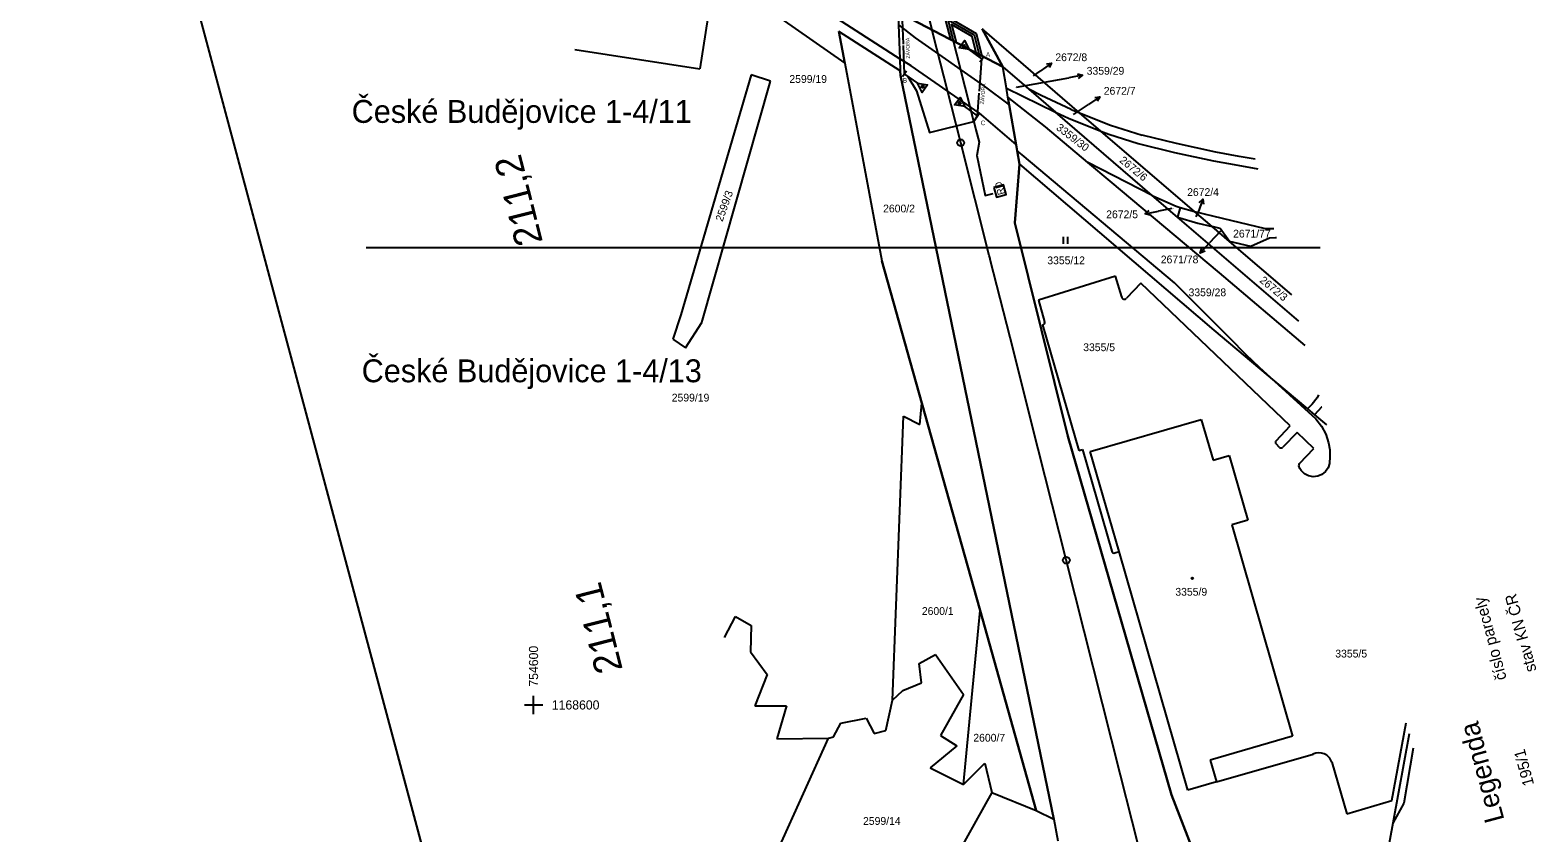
# Model space of a CAD drawing. Extents: x -754710 to -754206, y -1169123 to -1168234.
# Drawn here: x -754710 to -754380.5, y -1168628 to -1168452.5 of the extents above; entities that cross this region are included whole.
import ezdxf

# ---------------------------------------------------------------- set-up
doc = ezdxf.new("R2010")
doc.units = 0
for name, color, linetype in [('Implicitní', 7, 'Continuous'), ('Vrstva 1', 7, 'Continuous'), ('Vrstva 10', 7, 'Continuous'), ('Vrstva 16', 7, 'Continuous'), ('Vrstva 18', 7, 'Continuous'), ('Vrstva 19', 7, 'Continuous'), ('Vrstva 23', 7, 'Continuous'), ('Vrstva 25', 7, 'Continuous'), ('Vrstva 3', 7, 'Continuous'), ('Vrstva 4', 7, 'Continuous'), ('Vrstva 45', 7, 'Continuous'), ('Vrstva 6', 7, 'Continuous'), ('Vrstva 61', 7, 'Continuous'), ('Vrstva 7', 7, 'Continuous')]:
    doc.layers.add(name, color=color, linetype=linetype)

msp = doc.modelspace()

# ---------------------------------------------------------------- linework, layer by layer
at = {"layer": 'Implicitní'}
for points in [[(-754600, -1168602), (-754600, -1168600), (-754600, -1168598)], [(-754602, -1168600), (-754600, -1168600), (-754598, -1168600)]]:
    msp.add_lwpolyline(points, dxfattribs=at)
at = {"layer": 'Vrstva 1'}
for p, q in [((-754560.36, -1168439.85), (-754563.64, -1168460.96)), ((-754543.86, -1168443.35), (-754519.95, -1168458.75)), ((-754517.36, -1168450.11), (-754497.45, -1168460.53)), ((-754517.36, -1168450.11), (-754497.45, -1168460.53)), ((-754531.99, -1168459.75), (-754533.3, -1168452.78)), ((-754519.84, -1168461.42), (-754533.3, -1168452.78)), ((-754533.3, -1168452.78), (-754531.99, -1168459.75)), ((-754519.84, -1168461.42), (-754533.3, -1168452.78)), ((-754520.25, -1168451.35), (-754519.95, -1168458.75)), ((-754497.45, -1168460.53), (-754501.97, -1168452.25)), ((-754501.97, -1168452.25), (-754497.45, -1168460.53)), ((-754480.66, -1168470.56), (-754501.97, -1168452.25)), ((-754590.98, -1168456.71), (-754563.64, -1168460.96)), ((-754531.99, -1168459.75), (-754523.85, -1168502.96)), ((-754531.99, -1168459.75), (-754523.85, -1168502.96)), ((-754519.95, -1168458.75), (-754519.84, -1168461.42)), ((-754552.4, -1168462.3), (-754567.78, -1168514.73)), ((-754548.2, -1168463.7), (-754552.4, -1168462.3)), ((-754519.8, -1168462.41), (-754519.84, -1168461.42)), ((-754519.84, -1168461.42), (-754519.8, -1168462.41)), ((-754486.32, -1168624.94), (-754519.8, -1168462.41)), ((-754519.8, -1168462.41), (-754486.32, -1168624.94)), ((-754496.66, -1168465.16), (-754497.45, -1168460.53)), ((-754497.45, -1168460.53), (-754491.78, -1168465.4)), ((-754563.21, -1168516.41), (-754548.2, -1168463.7)), ((-754496.32, -1168467.13), (-754496.66, -1168465.16)), ((-754496.66, -1168465.16), (-754485.92, -1168470.44)), ((-754489.05, -1168466.81), (-754491.78, -1168465.4)), ((-754491.78, -1168465.4), (-754485.92, -1168470.44)), ((-754496.32, -1168467.13), (-754496.03, -1168468.86)), ((-754488.07, -1168473.66), (-754496.32, -1168467.13)), ((-754496.03, -1168468.86), (-754494.55, -1168477.55)), ((-754482.46, -1168469.84), (-754489.05, -1168466.81)), ((-754482.46, -1168469.84), (-754480.66, -1168470.56)), ((-754485.92, -1168470.44), (-754483.05, -1168471.75)), ((-754464.78, -1168488.62), (-754485.92, -1168470.44)), ((-754483.05, -1168471.75), (-754475.99, -1168474.58)), ((-754475.99, -1168474.58), (-754480.66, -1168470.56)), ((-754480.66, -1168470.56), (-754473.87, -1168473.28)), ((-754473.87, -1168473.28), (-754467, -1168475.47)), ((-754478.83, -1168481.43), (-754488.07, -1168473.66)), ((-754475.99, -1168474.58), (-754474.28, -1168475.26)), ((-754455.54, -1168492.15), (-754475.99, -1168474.58)), ((-754474.28, -1168475.26), (-754467.84, -1168477.28)), ((-754459.45, -1168477.29), (-754467, -1168475.47)), ((-754494.55, -1168477.55), (-754494.32, -1168478.89)), ((-754494.32, -1168478.89), (-754493.82, -1168481.8)), ((-754467.84, -1168477.28), (-754459.92, -1168479.25)), ((-754459.92, -1168479.25), (-754451.42, -1168481.08)), ((-754450.91, -1168479.15), (-754459.45, -1168477.29)), ((-754445.75, -1168480.12), (-754450.91, -1168479.15)), ((-754493.82, -1168481.8), (-754494.84, -1168494.63)), ((-754493.82, -1168481.8), (-754451.31, -1168518.1)), ((-754464.78, -1168488.62), (-754478.83, -1168481.43)), ((-754474, -1168485.49), (-754478.83, -1168481.43)), ((-754451.42, -1168481.08), (-754446.07, -1168482.05)), ((-754446.07, -1168482.05), (-754441.7, -1168482.79)), ((-754442.25, -1168480.73), (-754445.75, -1168480.12)), ((-754450.1, -1168505.56), (-754474, -1168485.49)), ((-754459.22, -1168493.4), (-754464.78, -1168488.62)), ((-754464.78, -1168488.62), (-754464, -1168489.01)), ((-754464, -1168489.01), (-754459.55, -1168491)), ((-754459.55, -1168491), (-754458.66, -1168491.26)), ((-754458.66, -1168491.26), (-754459.22, -1168493.4)), ((-754458.66, -1168491.26), (-754455.54, -1168492.15)), ((-754451.69, -1168495.45), (-754455.54, -1168492.15)), ((-754455.54, -1168492.15), (-754449.48, -1168493.64)), ((-754494.84, -1168494.63), (-754483.21, -1168541.23)), ((-754459.22, -1168493.4), (-754454.78, -1168494.69)), ((-754432.76, -1168516.15), (-754459.22, -1168493.4)), ((-754454.78, -1168494.69), (-754451.69, -1168495.45)), ((-754449.92, -1168495.89), (-754451.69, -1168495.45)), ((-754447.92, -1168498.69), (-754451.69, -1168495.45)), ((-754447.92, -1168498.69), (-754449.92, -1168495.89)), ((-754449.48, -1168493.64), (-754440.12, -1168495.87)), ((-754440.12, -1168495.87), (-754438.19, -1168495.88)), ((-754443.24, -1168499.78), (-754447.92, -1168498.69)), ((-754434.3, -1168510.39), (-754447.92, -1168498.69)), ((-754439.15, -1168497.98), (-754443.24, -1168499.78)), ((-754437.86, -1168497.94), (-754439.15, -1168497.98)), ((-754437.64, -1168497.93), (-754437.86, -1168497.94)), ((-754523.85, -1168502.96), (-754515.13, -1168534.05)), ((-754515.13, -1168534.05), (-754523.85, -1168502.96)), ((-754472.79, -1168506.27), (-754489.67, -1168511.5)), ((-754471.44, -1168510.82), (-754472.79, -1168506.27)), ((-754431.34, -1168521.47), (-754450.1, -1168505.56)), ((-754467.28, -1168507.81), (-754470.39, -1168511.07)), ((-754434.63, -1168539.02), (-754467.28, -1168507.81)), ((-754489.67, -1168511.5), (-754488.29, -1168516.29)), ((-754567.78, -1168514.73), (-754569.52, -1168520.08)), ((-754566.76, -1168521.95), (-754563.21, -1168516.41)), ((-754488.79, -1168516.94), (-754480.84, -1168544.38)), ((-754451.31, -1168518.1), (-754438.06, -1168529.24)), ((-754569.52, -1168520.08), (-754566.76, -1168521.95)), ((-754438.06, -1168529.24), (-754429.01, -1168537.46)), ((-754438.06, -1168529.24), (-754430.86, -1168535.3)), ((-754428.46, -1168532.2), (-754428.74, -1168532.86)), ((-754515.13, -1168534.05), (-754502.42, -1168579.34)), ((-754502.42, -1168579.34), (-754515.13, -1168534.05)), ((-754429.84, -1168534.28), (-754430.86, -1168535.3)), ((-754430.86, -1168535.3), (-754429.3, -1168536.61)), ((-754428.74, -1168532.86), (-754429.84, -1168534.28)), ((-754427.75, -1168534.95), (-754429.3, -1168536.61)), ((-754427.73, -1168534.92), (-754427.75, -1168534.95)), ((-754478.33, -1168544.59), (-754454.05, -1168537.59)), ((-754454.05, -1168537.59), (-754451.48, -1168546.52)), ((-754437.72, -1168542.25), (-754434.63, -1168539.02)), ((-754429.3, -1168536.61), (-754426.69, -1168538.8)), ((-754429.01, -1168537.46), (-754427.79, -1168539.04)), ((-754427.79, -1168539.04), (-754426.86, -1168540.83)), ((-754483.21, -1168541.23), (-754460.6, -1168619.67)), ((-754433.1, -1168540.48), (-754436.22, -1168543.69)), ((-754429.48, -1168543.95), (-754433.1, -1168540.48)), ((-754426.86, -1168540.83), (-754426.25, -1168542.73)), ((-754480.84, -1168544.38), (-754480.05, -1168544.18)), ((-754480.05, -1168544.18), (-754473.59, -1168566.41)), ((-754472.02, -1168566.47), (-754478.33, -1168544.59)), ((-754451.48, -1168546.52), (-754447.94, -1168545.46)), ((-754447.94, -1168545.46), (-754443.9, -1168559.58)), ((-754436.93, -1168543.71), (-754437.7, -1168542.95)), ((-754432.61, -1168547.25), (-754429.48, -1168543.95)), ((-754426.25, -1168542.73), (-754425.99, -1168544.22)), ((-754425.93, -1168545.71), (-754426.04, -1168547.24)), ((-754425.99, -1168544.22), (-754425.93, -1168545.71)), ((-754432.73, -1168547.73), (-754432.61, -1168547.25)), ((-754432.51, -1168548.29), (-754432.73, -1168547.73)), ((-754432.22, -1168548.77), (-754432.51, -1168548.29)), ((-754431.49, -1168549.46), (-754432.22, -1168548.77)), ((-754426.9, -1168548.99), (-754427.68, -1168549.62)), ((-754426.32, -1168548.19), (-754426.9, -1168548.99)), ((-754426.04, -1168547.24), (-754426.32, -1168548.19)), ((-754430.61, -1168549.91), (-754431.49, -1168549.46)), ((-754429.64, -1168550.11), (-754430.61, -1168549.91)), ((-754428.62, -1168549.99), (-754429.64, -1168550.11)), ((-754427.68, -1168549.62), (-754428.62, -1168549.99)), ((-754443.9, -1168559.58), (-754447.41, -1168560.64)), ((-754447.41, -1168560.64), (-754434.1, -1168606.84)), ((-754471.68, -1168615.35), (-754483.58, -1168568.3)), ((-754472.98, -1168566.77), (-754472.02, -1168566.47)), ((-754456.98, -1168618.63), (-754472.02, -1168566.47)), ((-754502.42, -1168579.34), (-754490.14, -1168623.07)), ((-754490.14, -1168623.07), (-754502.42, -1168579.34)), ((-754412.42, -1168620.92), (-754409.25, -1168603.88)), ((-754434.1, -1168606.84), (-754452.14, -1168612.04)), ((-754408.6, -1168606.31), (-754412.19, -1168625.83)), ((-754450.76, -1168616.84), (-754429.64, -1168610.75)), ((-754407.76, -1168609.45), (-754409.8, -1168621.48)), ((-754452.14, -1168612.04), (-754450.76, -1168616.84)), ((-754425.55, -1168612.51), (-754422.27, -1168623.78)), ((-754463.59, -1168647.3), (-754471.68, -1168615.35)), ((-754450.76, -1168616.84), (-754456.98, -1168618.63)), ((-754460.6, -1168619.67), (-754452.67, -1168639.96)), ((-754422.27, -1168623.78), (-754412.42, -1168620.92)), ((-754409.8, -1168621.48), (-754412.19, -1168625.83)), ((-754490.14, -1168623.07), (-754486.32, -1168624.94)), ((-754490.14, -1168623.07), (-754486.32, -1168624.94)), ((-754486.32, -1168624.94), (-754485.38, -1168629.68)), ((-754412.19, -1168625.83), (-754413.36, -1168632.2))]:
    msp.add_line(p, q, dxfattribs=at)
for points in [[(-754483.58, -1168568.3), (-754489.69, -1168544.13), (-754495.86, -1168519.7), (-754500.17, -1168502.64), (-754500.22, -1168502.46), (-754500.39, -1168501.79), (-754506.63, -1168477.15), (-754508.73, -1168468.84), (-754512.62, -1168453.46), (-754513.24, -1168451.02), (-754516.47, -1168438.36), (-754517.79, -1168433.24), (-754523.55, -1168411.48), (-754527.19, -1168398.27), (-754531.51, -1168382.98), (-754533.99, -1168374.26), (-754535.88, -1168367.71), (-754539.68, -1168354.44)], [(-754519.17, -1168455.59), (-754519.47, -1168446.86)], [(-754452.67, -1168639.96), (-754460.6, -1168619.67), (-754483.21, -1168541.23), (-754494.84, -1168494.63), (-754493.82, -1168481.8), (-754494.32, -1168478.89), (-754494.55, -1168477.55), (-754496.03, -1168468.86), (-754496.32, -1168467.13), (-754496.66, -1168465.16), (-754497.45, -1168460.53), (-754517.36, -1168450.11), (-754520.37, -1168448.54), (-754520.33, -1168449.52), (-754520.25, -1168451.35), (-754519.95, -1168458.75), (-754519.84, -1168461.42), (-754519.8, -1168462.41), (-754486.32, -1168624.94), (-754485.38, -1168629.68)], [(-754518.94, -1168462.12), (-754519.16, -1168455.85)], [(-754502.54, -1168465.84), (-754501.99, -1168458.81)], [(-754502.96, -1168471.26), (-754502.57, -1168466.27)]]:
    msp.add_lwpolyline(points, dxfattribs=at)
for centre in [(-754506.63, -1168477.14), (-754483.56, -1168568.36), (-754483.56, -1168568.36)]:
    msp.add_circle(centre, 0.75, dxfattribs=at)
for centre, radius, start, end in [((-754470.87, -1168510.77), 0.567, 184.6224, 328.5926), ((-754488.79, -1168516.42), 0.517, 269.9303, 14.9325), ((-754437.38, -1168542.59), 0.482, 135.0258, 228.2473), ((-754436.59, -1168543.32), 0.518, 228.3065, 314.9206), ((-754473.14, -1168566.34), 0.458, 188.7847, 290.1201), ((-754428.36, -1168613.4), 2.94, 17.5572, 115.8766)]:
    msp.add_arc(centre, radius, start, end, dxfattribs=at)
at = {"layer": 'Vrstva 10'}
msp.add_lwpolyline([(-754509.03, -1168449.86), (-754503.24, -1168453.23), (-754502.05, -1168458.12), (-754503.23, -1168457.5), (-754504.12, -1168453.89), (-754508.62, -1168451.26), (-754507.63, -1168455.2), (-754508.81, -1168454.58), (-754509.87, -1168450.43)], dxfattribs=at)
at = {"layer": 'Vrstva 16'}
for p, q in [((-754486.8, -1168459.72), (-754489.25, -1168461.45)), ((-754494.41, -1168464.98), (-754483, -1168462.92)), ((-754490.7, -1168462.48), (-754489.25, -1168461.45)), ((-754480.05, -1168462.39), (-754483, -1168462.92)), ((-754481.95, -1168470.96), (-754478.71, -1168468.75)), ((-754476.23, -1168467.06), (-754478.71, -1168468.75)), ((-754453.69, -1168489.47), (-754454.76, -1168492.27)), ((-754466.33, -1168492.63), (-754463.38, -1168492.06)), ((-754460.46, -1168491.5), (-754463.38, -1168492.06)), ((-754455.16, -1168493.3), (-754454.76, -1168492.27)), ((-754449.84, -1168496.45), (-754452.23, -1168499.03)), ((-754454.27, -1168501.23), (-754452.23, -1168499.03))]:
    msp.add_line(p, q, dxfattribs=at)
for points in [[(-754487.91, -1168459.89), (-754486.8, -1168459.72), (-754487.33, -1168460.7)], [(-754481.12, -1168462.07), (-754480.05, -1168462.39), (-754480.94, -1168463.06)], [(-754477.34, -1168467.21), (-754476.23, -1168467.06), (-754476.78, -1168468.03)], [(-754454.51, -1168490.22), (-754453.69, -1168489.47), (-754453.58, -1168490.58)], [(-754465.25, -1168492.93), (-754466.33, -1168492.63), (-754465.44, -1168491.95)], [(-754453.22, -1168500.84), (-754454.27, -1168501.23), (-754453.95, -1168500.16)]]:
    msp.add_lwpolyline(points, dxfattribs=at)
at = {"layer": 'Vrstva 23'}
msp.add_lwpolyline([(-754499.42, -1168486.91), (-754498.83, -1168489.01), (-754496.71, -1168488.44), (-754497.31, -1168486.34), (-754499.42, -1168486.91)], dxfattribs=at)
at = {"layer": 'Vrstva 25'}
for p, q in [((-754484.19, -1168499.21), (-754484.19, -1168497.71)), ((-754483.19, -1168499.21), (-754483.19, -1168497.71))]:
    msp.add_line(p, q, dxfattribs=at)
msp.add_circle((-754456.02, -1168572.33), 0.175, dxfattribs=at)
at = {"layer": 'Vrstva 3'}
msp.add_lwpolyline([(-754710.01, -1168311.22), (-754492.6, -1169122.6), (-754205.72, -1169045.73), (-754423.13, -1168234.35)], close=True, dxfattribs=at)
msp.add_lwpolyline([(-754636.61, -1168500), (-754428.06, -1168500)], dxfattribs=at)
at = {"layer": 'Vrstva 4'}
for p, q in [((-754520.25, -1168451.35), (-754516.61, -1168454.2)), ((-754516.61, -1168454.2), (-754501.51, -1168464.78)), ((-754505.88, -1168456.22), (-754505.95, -1168455.73)), ((-754517.48, -1168460.34), (-754519.95, -1168458.75)), ((-754502.45, -1168459.44), (-754501.53, -1168458.18)), ((-754518.49, -1168461.48), (-754519.39, -1168462.75)), ((-754502.71, -1168470.6), (-754517.48, -1168460.34)), ((-754515.01, -1168464.65), (-754514.93, -1168465.13)), ((-754501.51, -1168464.78), (-754496.03, -1168468.86)), ((-754506.85, -1168468.67), (-754506.92, -1168468.19)), ((-754503.42, -1168471.89), (-754502.5, -1168470.64)), ((-754502.71, -1168470.6), (-754494.55, -1168477.55)), ((-754493.21, -1168479.76), (-754494.32, -1168478.89)), ((-754459.9, -1168507.75), (-754493.21, -1168479.76)), ((-754447.78, -1168519.94), (-754459.9, -1168507.75)), ((-754444.25, -1168523.49), (-754447.78, -1168519.94)), ((-754441.31, -1168526.26), (-754444.25, -1168523.49)), ((-754438.06, -1168529.24), (-754441.31, -1168526.26))]:
    msp.add_line(p, q, dxfattribs=at)
for points in [[(-754501.99, -1168458.81), (-754504.79, -1168456.76), (-754507, -1168456.37), (-754505.82, -1168454.75), (-754504.79, -1168456.76)], [(-754518.94, -1168462.12), (-754516.1, -1168464.12), (-754513.9, -1168464.48), (-754515.05, -1168466.11), (-754516.1, -1168464.12)], [(-754502.96, -1168471.26), (-754505.77, -1168469.21), (-754507.97, -1168468.82), (-754506.79, -1168467.2), (-754505.77, -1168469.21)]]:
    msp.add_lwpolyline(points, dxfattribs=at)
for centre in [(-754505.91, -1168455.97), (-754514.97, -1168464.89), (-754506.89, -1168468.43)]:
    msp.add_circle(centre, 0.248, dxfattribs=at)
at = {"layer": 'Vrstva 45'}
msp.add_line((-754503.77, -1168472.48), (-754502.96, -1168471.26), dxfattribs=at)
for points in [[(-754503.77, -1168472.48), (-754509.4, -1168450.23)], [(-754509.4, -1168450.23), (-754503.68, -1168453.56), (-754502.47, -1168458.49), (-754501.99, -1168458.81)], [(-754518.94, -1168462.12), (-754518.19, -1168462.65), (-754516.3, -1168465.76), (-754513.47, -1168474.91), (-754503.77, -1168472.48)], [(-754503.77, -1168472.48), (-754503.3, -1168474.33)], [(-754503.3, -1168474.33), (-754502.62, -1168477.03), (-754503.11, -1168479.94), (-754501.32, -1168488.67), (-754499.51, -1168488.21)]]:
    msp.add_lwpolyline(points, dxfattribs=at)
at = {"layer": 'Vrstva 6'}
for p, q in [((-754560.36, -1168439.85), (-754531.99, -1168459.75)), ((-754515.57, -1168538.69), (-754515.13, -1168534.05)), ((-754521.52, -1168598.96), (-754519.11, -1168536.88)), ((-754519.11, -1168536.88), (-754515.57, -1168538.69)), ((-754558.26, -1168585.26), (-754555.83, -1168580.68)), ((-754555.83, -1168580.68), (-754552.45, -1168582.65)), ((-754506.06, -1168617.39), (-754502.42, -1168579.34)), ((-754552.45, -1168582.65), (-754552.61, -1168588.39)), ((-754552.61, -1168588.39), (-754548.9, -1168593.37)), ((-754515.73, -1168590.96), (-754512.18, -1168588.99)), ((-754515.24, -1168595.19), (-754515.73, -1168590.96)), ((-754512.18, -1168588.99), (-754506.06, -1168597.75)), ((-754548.9, -1168593.37), (-754551.64, -1168600.17)), ((-754519.27, -1168596.85), (-754515.24, -1168595.19)), ((-754521.52, -1168598.96), (-754519.27, -1168596.85)), ((-754506.06, -1168597.75), (-754511.06, -1168606.67)), ((-754551.64, -1168600.17), (-754544.72, -1168600.17)), ((-754544.72, -1168600.17), (-754546.81, -1168607.42)), ((-754522.97, -1168605.61), (-754521.52, -1168598.96)), ((-754534.41, -1168606.97), (-754532.8, -1168603.95)), ((-754532.8, -1168603.95), (-754527.32, -1168602.89)), ((-754527.32, -1168602.89), (-754525.55, -1168606.21)), ((-754546.81, -1168607.42), (-754535.54, -1168607.27)), ((-754546.49, -1168631.48), (-754535.54, -1168607.27)), ((-754535.54, -1168607.27), (-754534.41, -1168606.97)), ((-754525.55, -1168606.21), (-754522.97, -1168605.61)), ((-754511.06, -1168606.67), (-754507.51, -1168608.93)), ((-754507.51, -1168608.93), (-754513.31, -1168613.76)), ((-754513.31, -1168613.76), (-754506.06, -1168617.39)), ((-754506.06, -1168617.39), (-754501.39, -1168612.71)), ((-754501.39, -1168612.71), (-754499.81, -1168619.14)), ((-754499.81, -1168619.14), (-754513.7, -1168643.9)), ((-754499.81, -1168619.14), (-754490.14, -1168623.07))]:
    msp.add_line(p, q, dxfattribs=at)
at = {"layer": 'Vrstva 61'}
msp.add_line((-754710.01, -1168311.22), (-754492.6, -1169122.6), dxfattribs=at)

# ---------------------------------------------------------------- texts
at = {"layer": 'Implicitní'}
msp.add_text('754600', height=2, rotation=90, dxfattribs=at).set_placement((-754599, -1168596))
msp.add_text('1168600', height=2, dxfattribs=at).set_placement((-754596, -1168601))
at = {"layer": 'Vrstva 16'}
for s, p in [('2672/8', (-754485.95, -1168459.29)), ('3359/29', (-754479.1, -1168462.25)), ('2672/7', (-754475.37, -1168466.63)), ('2672/4', (-754457.15, -1168488.76)), ('2672/5', (-754474.84, -1168493.62)), ('2671/78', (-754462.91, -1168503.48))]:
    msp.add_text(s, height=1.7, dxfattribs=at).set_placement(p)
at = {"layer": 'Vrstva 18'}
for s, height, p in [('2599/19', 1.7, (-754544.08, -1168464.04)), ('2672/8', 0.1, (-754490.69, -1168462.48)), ('3359/29', 0.1, (-754494.71, -1168464.98)), ('2672/7', 0.1, (-754481.94, -1168470.96)), ('2600/2', 1.7, (-754523.59, -1168492.35)), ('2672/5', 0.1, (-754460.45, -1168491.5)), ('2672/4', 0.1, (-754455.15, -1168493.3)), ('2671/78', 0.1, (-754449.83, -1168496.45)), ('2671/77', 1.7, (-754447.1, -1168497.84)), ('3355/12', 1.7, (-754487.71, -1168503.68)), ('3359/28', 1.7, (-754456.84, -1168510.67)), ('3355/5', 1.7, (-754479.86, -1168522.67)), ('2599/19', 1.7, (-754569.79, -1168533.68)), ('2600/1', 1.7, (-754515.13, -1168580.33)), ('3355/5', 1.7, (-754424.77, -1168589.63)), ('2600/7', 1.7, (-754503.88, -1168608.02)), ('2599/14', 1.7, (-754527.98, -1168626.21))]:
    msp.add_text(s, height=height, dxfattribs=at).set_placement(p)
for s, rotation, p in [('3359/30', 322.3461, (-754485.91, -1168474.12)), ('2672/6', 320.398, (-754472.08, -1168481.22)), ('2599/3', 70.1873, (-754558.71, -1168494.49)), ('2672/3', 320.398, (-754441.44, -1168507.45))]:
    msp.add_text(s, height=1.7, rotation=rotation, dxfattribs=at).set_placement(p)
at = {"layer": 'Vrstva 19'}
msp.add_text('3355/9', height=1.7, dxfattribs=at).set_placement((-754459.73, -1168576.12))
at = {"layer": 'Vrstva 23'}
msp.add_text('RD', height=1.5, rotation=105.7615, dxfattribs=at).set_placement((-754497.01, -1168488.28))
at = {"layer": 'Vrstva 3'}
for s, p in [('České Budějovice 1-4/11', (-754639.74, -1168472.78)), ('České Budějovice 1-4/13', (-754637.55, -1168529.47))]:
    msp.add_text(s, height=5, dxfattribs=at).set_placement(p)
for s, height, p in [('číslo parcely', 2.52, (-754387.28, -1168594.26)), ('stav KN ČR', 2.52, (-754380.76, -1168592.46)), ('Legenda', 4.32, (-754387.77, -1168625.09)), ('195/1', 2.448, (-754381.29, -1168617.36))]:
    msp.add_text(s, height=height, rotation=105.021, dxfattribs=at).set_placement(p)
at = {"layer": 'Vrstva 4'}
for rotation, p in [(92.0732, (-754517.71, -1168458.7)), (85.5249, (-754501.56, -1168468.73))]:
    msp.add_text('ZÁVORA', height=0.8, rotation=rotation, dxfattribs=at).set_placement(p)
for s, p in [('A', (-754501.12, -1168458.33)), ('B', (-754519.28, -1168463.99)), ('C', (-754502.25, -1168473.28))]:
    msp.add_text(s, height=1, dxfattribs=at).set_placement(p)
at = {"layer": 'Vrstva 7'}
for s, rotation, p in [('211,2', 104.1901, (-754597.93, -1168498.79)), ('211,1', 104.1906, (-754580.47, -1168592.24))]:
    msp.add_text(s, height=6, rotation=rotation, dxfattribs=at).set_placement(p)

doc.saveas('drawing.dxf')
